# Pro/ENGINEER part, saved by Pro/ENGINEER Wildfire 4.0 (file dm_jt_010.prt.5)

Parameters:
  METRIC = "NO"

Other parameters: PITCH, DRILL_POINT_ANGLE, DRILL_DEPTH, DRILL_DIAMETER, THREAD_DIAMETER, THREADS_PER_INCH, THREAD_DEPTH, THREAD_LENGTH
